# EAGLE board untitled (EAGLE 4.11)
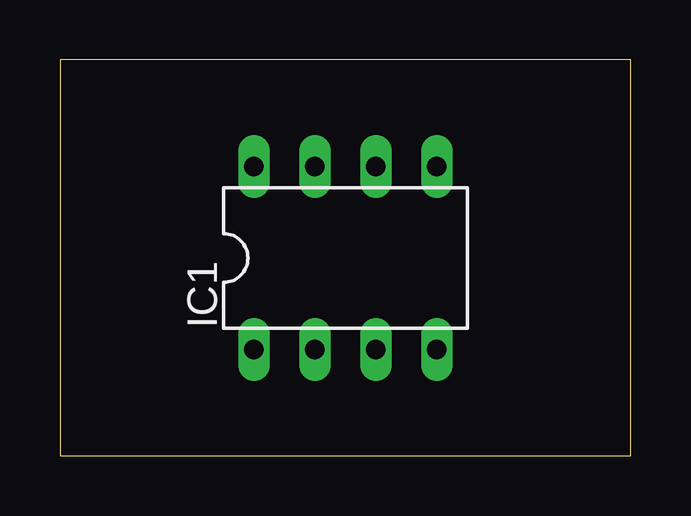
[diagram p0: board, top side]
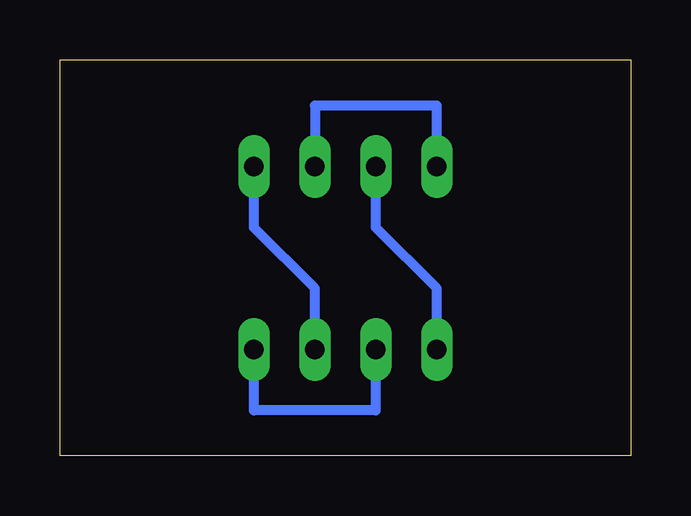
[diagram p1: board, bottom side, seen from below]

Size 23.8 x 16.5 mm. Coordinates in mm from the lower left corner, seen from the top.
Outline: 0,0 23.8,0 23.8,16.5 0,16.5 0,0
Copper layers (1*16): Top 0.035mm / dielectric 1.5mm / Bottom 0.035mm
Design rules "default": minimum track width 10mil, minimum drill 24mil, track to track 8mil, track to pad 8mil, pad to pad 8mil, via to via 8mil, smd to smd 8mil, copper to edge 40mil, drill to drill 8mil, minimum pad ring 10mil, minimum via ring 8mil, stop-mask expansion 4mil, vias tented up to drill 0mil, thermal gap 10mil

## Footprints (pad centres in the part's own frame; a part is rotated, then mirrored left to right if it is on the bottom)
DIL08 = drill 0.813 long: 1 -3.81,-3.81; 2 -1.27,-3.81; 3 1.27,-3.81; 4 3.81,-3.81; 5 3.81,3.81; 6 1.27,3.81; 7 -1.27,3.81; 8 -3.81,3.81

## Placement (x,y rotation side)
IC1  LM741P  [DIL08]  11.9,8.25 0 top

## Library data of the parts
IC1 = linear

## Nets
N$1: IC1.2 IC1.4
N$2: IC1.3 IC1.5
N$3: IC1.1 IC1.7
N$4: IC1.6 IC1.8

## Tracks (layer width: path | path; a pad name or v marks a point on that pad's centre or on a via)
N$1
  Bottom 0.406: IC1.2 10.63,1.9 15.71,1.9 IC1.4
N$2
  Bottom 0.406: IC1.5 15.71,9.52 13.17,6.98 IC1.3
N$3
  Bottom 0.406: IC1.1 8.09,6.98 10.63,9.52 IC1.7
N$4
  Bottom 0.406: IC1.8 8.09,14.6 13.17,14.6 IC1.6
